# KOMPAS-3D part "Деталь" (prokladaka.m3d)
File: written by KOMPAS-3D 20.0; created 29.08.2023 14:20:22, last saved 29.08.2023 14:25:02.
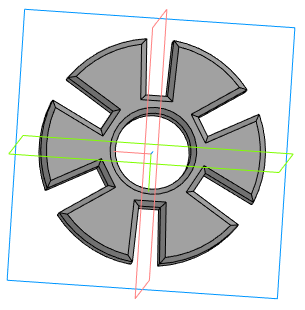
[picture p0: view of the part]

Document properties: Полное имя файла: D:\прокладка.m3d

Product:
- Part/product: Деталь
    Масса: 0.0588868

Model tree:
1. Эскиз:1
2. Элемент выдавливания:1
     Расстояние 1 = 8.5
3. Эскиз:2  (with: Элемент выдавливания:1)
4. Элемент выдавливания:2
     Расстояние 2 = 10
5. Массив по концентрической сетке:1  (with: Элемент выдавливания:2, Элемент выдавливания:1)  (6 pattern instances)
     Шаг 2 = 360
6. Эскиз:3  (with: Элемент выдавливания:1)
7. Элемент выдавливания:3
     Расстояние 2 = 10
8. Фаска:1  (with: Элемент выдавливания:1)
     Угол = 45; Длина 1 = 1; Длина 2 = 1
9. Фаска:2  (with: Элемент выдавливания:1)
     Угол = 45; Длина 1 = 1; Длина 2 = 1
